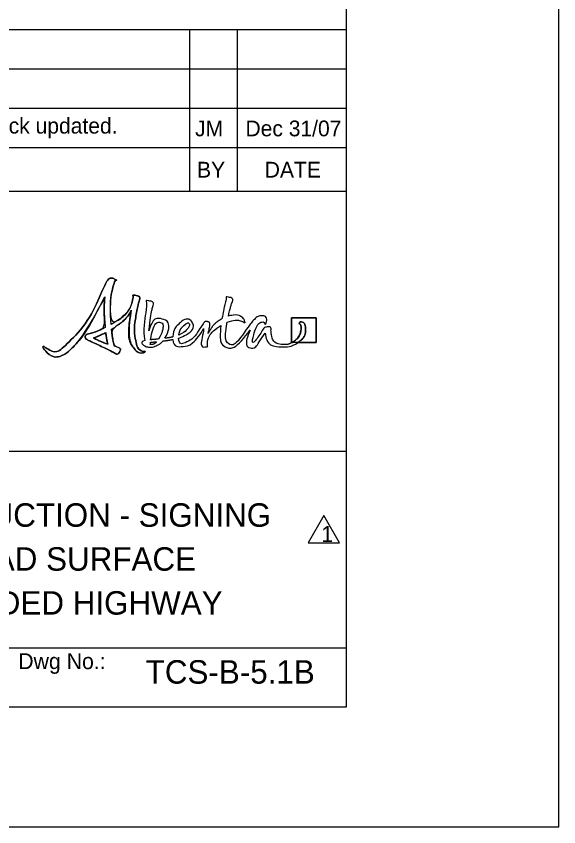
# Model space of a CAD drawing. Extents: x 1351 to 1567, y 178 to 457.
# Drawn here: x 1518.5 to 1567.4, y 177.9 to 251 of the extents above; entities that cross this region are included whole.
import ezdxf

# ---------------------------------------------------------------- set-up
doc = ezdxf.new("R2010")
doc.units = 0
doc.layers.add('Level 53', color=7, linetype='Continuous')
doc.layers.add('Level 60', color=7, linetype='Continuous')

msp = doc.modelspace()

# ---------------------------------------------------------------- linework, layer by layer
at = {"layer": 'Level 53'}
msp.add_line((1543.914, 221.573), (1543.364, 221.573), dxfattribs=at)
msp.add_lwpolyline([(1543.914, 221.573), (1545.53, 221.573), (1545.53, 223.804), (1543.3, 223.804), (1543.3, 221.573), (1543.364, 221.573)], dxfattribs=at)
for points, degree in [([(1529.929, 220.764), (1529.69, 220.8), (1529.375, 221.126), (1529.28, 221.663), (1529.109, 222.629), (1529.21, 223.583), (1529.494, 225.004), (1529.548, 225.273), (1529.732, 225.739), (1529.148, 225.829), (1528.963, 225.857), (1529.059, 225.766), (1529.007, 225.52), (1528.782, 224.461), (1527.917, 223.699), (1527.048, 223.188), (1526.957, 224.399), (1526.994, 225.745), (1527.222, 226.57), (1527.414, 227.266), (1527.643, 227.138), (1527.359, 227.285), (1527.061, 227.439), (1526.74, 227.235), (1526.48, 226.717), (1526.22, 226.198), (1525.023, 223.382), (1523.112, 221.482), (1522.134, 220.509), (1521.249, 221.01), (1521.072, 221.159), (1520.928, 221.281), (1520.875, 221.093), (1521.053, 220.901), (1521.845, 220.048), (1523, 220.537), (1523.421, 220.958), (1524.584, 222.12), (1525.936, 224.622), (1526.483, 225.684), (1526.432, 225.086), (1526.416, 224.083), (1526.527, 222.909), (1525.935, 222.62), (1525.404, 222.451), (1525.154, 222.385), (1524.883, 222.314), (1524.715, 222.203), (1524.71, 222.078), (1524.705, 221.94), (1524.887, 221.824), (1525.15, 221.699), (1525.619, 221.477), (1526.99, 220.829), (1527.328, 220.632), (1527.618, 220.464), (1527.759, 220.596), (1527.845, 220.777), (1527.957, 221.013), (1527.65, 221.149), (1527.352, 221.238), (1527.238, 221.636), (1527.146, 222.172), (1527.085, 222.762), (1527.783, 223.191), (1528.47, 223.763), (1528.865, 224.477), (1528.766, 223.88), (1528.51, 221.849), (1529.151, 220.991), (1529.292, 220.802), (1529.604, 220.595), (1529.908, 220.626), (1530.051, 220.64), (1530.124, 220.734), (1530.11, 220.764), (1530.095, 220.793), (1530.013, 220.752), (1529.929, 220.764)], 3), ([(1527.048, 223.188), (1526.957, 224.399), (1526.994, 225.745), (1527.222, 226.57), (1527.414, 227.266), (1527.643, 227.138), (1527.359, 227.285), (1527.061, 227.439), (1526.74, 227.235), (1526.48, 226.717), (1526.22, 226.198), (1525.023, 223.382), (1523.112, 221.482), (1522.134, 220.509), (1521.249, 221.01), (1521.072, 221.159), (1520.928, 221.281), (1520.875, 221.093), (1521.053, 220.901), (1521.845, 220.048), (1523, 220.537), (1523.421, 220.958), (1524.584, 222.12), (1525.936, 224.622), (1526.483, 225.684)], 3), ([(1529.929, 220.764), (1529.69, 220.8), (1529.375, 221.126), (1529.28, 221.663), (1529.109, 222.629), (1529.21, 223.583), (1529.494, 225.004), (1529.548, 225.273), (1529.732, 225.739), (1529.148, 225.829), (1528.963, 225.857), (1529.059, 225.766), (1529.007, 225.52), (1528.782, 224.461), (1527.917, 223.699), (1527.048, 223.188)], 3), ([(1526.483, 225.684), (1526.432, 225.086), (1526.416, 224.083), (1526.527, 222.909)], 2), ([(1530.466, 222.606), (1530.512, 223.174), (1530.603, 223.867), (1530.731, 224.51), (1530.785, 224.779), (1530.969, 225.244), (1530.385, 225.334), (1530.2, 225.363), (1530.228, 225.276), (1530.244, 225.025), (1530.265, 224.688), (1529.892, 222.649), (1530.086, 221.753)], 3), ([(1537.62, 223.947), (1537.685, 224.244), (1537.76, 224.546), (1537.843, 224.84), (1537.918, 225.109), (1538.139, 225.575), (1537.562, 225.664), (1537.379, 225.693), (1537.457, 225.604), (1537.396, 225.356), (1537.285, 224.898), (1537.144, 224.306), (1537.043, 223.71)], 3), ([(1527.085, 222.762), (1527.783, 223.191), (1528.47, 223.763), (1528.865, 224.477)], 2), ([(1528.865, 224.477), (1528.766, 223.88), (1528.51, 221.849), (1529.151, 220.991), (1529.292, 220.802), (1529.604, 220.595), (1529.908, 220.626), (1530.051, 220.64), (1530.124, 220.734), (1530.11, 220.764), (1530.095, 220.793), (1530.013, 220.752), (1529.929, 220.764)], 3), ([(1531.904, 221.944), (1532.318, 222.617), (1532.283, 223.527), (1531.676, 223.68), (1530.972, 223.858), (1530.616, 223.174), (1530.466, 222.606)], 3), ([(1533.13, 221.967), (1533.226, 221.996), (1533.312, 222.027), (1533.385, 222.059), (1534.268, 222.451), (1534.571, 223.041), (1534.347, 223.4), (1534.134, 223.741), (1533.525, 223.638), (1533.044, 223.131), (1532.807, 222.882), (1532.625, 222.453), (1532.604, 222.063)], 3), ([(1537.043, 223.71), (1536.569, 223.437), (1536.128, 222.981), (1535.804, 222.381)], 2), ([(1542.675, 221.375), (1541.759, 221.375), (1541.523, 222.087), (1541.479, 222.439), (1541.45, 222.673), (1541.5, 223.012), (1541.096, 222.967), (1540.813, 222.935), (1540.557, 222.384), (1540.198, 221.92), (1539.89, 221.521), (1539.752, 221.559), (1539.824, 221.902), (1539.913, 222.33), (1540.27, 223.335), (1540.68, 223.409), (1540.869, 223.442), (1540.936, 223.11), (1541.023, 223.318), (1541.111, 223.526), (1541.031, 223.976), (1540.607, 223.976), (1540.311, 223.976), (1539.955, 223.662), (1539.663, 223.304), (1539.409, 222.992), (1538.124, 221.1), (1537.585, 221.508), (1537.333, 221.699), (1537.353, 222.477), (1537.512, 223.393)], 3), ([(1537.512, 223.393), (1538.151, 223.639), (1538.683, 223.559), (1538.984, 223.414), (1539.133, 223.343), (1539.153, 223.353), (1539.09, 223.517), (1538.996, 223.757), (1538.482, 224.132), (1537.678, 223.96), (1537.659, 223.956), (1537.639, 223.951), (1537.62, 223.947)], 3), ([(1543.3, 223.804), (1543.3, 223.804), (1543.3, 221.573), (1543.3, 221.573), (1543.3, 221.573), (1543.364, 221.573), (1543.364, 221.573), (1543.848, 221.863), (1544.174, 222.417), (1544.173, 222.873), (1544.173, 223.267), (1543.964, 223.247), (1543.988, 223.302), (1544.055, 223.46), (1544.548, 223.37), (1544.577, 222.814), (1544.601, 222.342), (1544.354, 221.886), (1543.914, 221.573), (1543.914, 221.573), (1545.53, 221.573), (1545.53, 221.573), (1545.53, 221.573), (1545.53, 223.804), (1545.53, 223.804), (1545.53, 223.804), (1543.3, 223.804), (1543.3, 223.804)], 3), ([(1526.527, 222.909), (1525.935, 222.62), (1525.404, 222.451), (1525.154, 222.385), (1524.883, 222.314), (1524.715, 222.203), (1524.71, 222.078), (1524.705, 221.94), (1524.887, 221.824), (1525.15, 221.699), (1525.619, 221.477), (1526.99, 220.829), (1527.328, 220.632), (1527.618, 220.464), (1527.759, 220.596), (1527.845, 220.777), (1527.957, 221.013), (1527.65, 221.149), (1527.352, 221.238)], 3), ([(1530.616, 221.815), (1530.711, 222.531), (1531.083, 223.526), (1531.547, 223.366), (1531.814, 223.274), (1531.674, 222.435), (1531.331, 221.878)], 3), ([(1532.61, 221.842), (1532.659, 221.449), (1532.915, 221.148), (1533.51, 221.203), (1534.357, 221.282), (1535.108, 222.322), (1535.392, 222.823)], 3), ([(1535.804, 222.381), (1535.86, 222.658), (1535.947, 222.964), (1535.953, 223.17), (1535.959, 223.388), (1535.81, 223.436), (1535.752, 223.453), (1535.626, 223.489), (1535.473, 223.426), (1535.322, 223.213), (1534.969, 222.716), (1534.522, 221.929), (1533.843, 221.598), (1533.356, 221.362), (1533.142, 221.6), (1533.13, 221.967)], 3), ([(1533.602, 223.086), (1533.898, 223.361), (1534.045, 223.341), (1534.084, 223.267), (1534.168, 223.108), (1533.819, 222.545), (1533.152, 222.237)], 3), ([(1533.152, 222.237), (1533.21, 222.54), (1533.369, 222.87), (1533.602, 223.086)], 2), ([(1535.392, 222.823), (1535.341, 222.286), (1534.991, 221.113), (1535.587, 221.173), (1535.821, 221.197), (1535.719, 221.234), (1535.734, 221.436), (1535.785, 222.142), (1536.373, 222.741), (1536.955, 223.108)], 3), ([(1536.955, 223.108), (1536.854, 222.243), (1536.889, 221.47), (1537.282, 221.225), (1538.004, 220.773), (1539.026, 221.962), (1539.589, 222.689)], 3), ([(1543.364, 221.573), (1543.848, 221.863), (1544.174, 222.417), (1544.173, 222.873), (1544.173, 223.267), (1543.964, 223.247), (1543.988, 223.302), (1544.055, 223.46), (1544.548, 223.37), (1544.577, 222.814), (1544.601, 222.342), (1544.354, 221.886), (1543.914, 221.573)], 3), ([(1525.457, 221.976), (1525.766, 222.089), (1526.159, 222.254), (1526.573, 222.471)], 2), ([(1525.457, 221.976), (1525.766, 222.089), (1526.159, 222.254), (1526.573, 222.471), (1526.629, 221.998), (1526.69, 221.655), (1526.757, 221.402), (1526.454, 221.512), (1526.022, 221.688), (1525.457, 221.976)], 3), ([(1526.573, 222.471), (1526.629, 221.998), (1526.69, 221.655), (1526.757, 221.402)], 2), ([(1527.352, 221.238), (1527.238, 221.636), (1527.146, 222.172), (1527.085, 222.762)], 2), ([(1539.589, 222.689), (1539.302, 222.044), (1539.14, 221.216), (1539.571, 221.09), (1540.075, 220.943), (1540.473, 221.78), (1540.939, 222.421)], 3), ([(1540.939, 222.421), (1540.993, 221.961), (1541.3, 221.168), (1542.537, 221.168), (1543.093, 221.168), (1543.565, 221.325), (1543.914, 221.573)], 3), ([(1526.757, 221.402), (1526.454, 221.512), (1526.022, 221.688), (1525.457, 221.976)], 2), ([(1530.086, 221.753), (1529.835, 221.672), (1529.733, 221.483), (1530.056, 221.284), (1530.279, 221.146), (1530.769, 221.101), (1531.264, 221.345), (1531.441, 221.432), (1531.595, 221.555), (1531.723, 221.7)], 3), ([(1530.541, 221.383), (1530.573, 221.41), (1530.593, 221.45), (1530.593, 221.498), (1530.593, 221.529), (1530.594, 221.561), (1530.595, 221.593)], 3), ([(1530.743, 221.384), (1530.661, 221.372), (1530.594, 221.373), (1530.541, 221.383)], 2), ([(1530.595, 221.593), (1530.721, 221.599), (1530.918, 221.613), (1531.152, 221.636)], 2), ([(1531.331, 221.878), (1531.106, 221.855), (1530.868, 221.834), (1530.616, 221.815)], 2), ([(1531.152, 221.636), (1531.029, 221.501), (1530.891, 221.407), (1530.743, 221.384)], 2), ([(1531.723, 221.7), (1532.018, 221.738), (1532.328, 221.785), (1532.61, 221.842)], 2), ([(1532.604, 222.063), (1532.4, 222.018), (1532.165, 221.979), (1531.904, 221.944)], 2), ([(1543.364, 221.573), (1543.159, 221.451), (1542.925, 221.375), (1542.675, 221.375)], 2)]:
    msp.add_open_spline(points, degree=degree, dxfattribs=at)
at = {"layer": 'Level 60'}
for p, q in [((1548.312, 249.746), (1484.432, 249.746)), ((1548.312, 249.746), (1484.432, 249.746)), ((1534.118, 249.746), (1534.118, 235.196)), ((1534.118, 249.746), (1534.118, 235.196)), ((1538.429, 249.746), (1538.429, 235.196)), ((1538.429, 249.746), (1538.429, 235.196)), ((1548.312, 246.197), (1484.432, 246.197)), ((1548.312, 246.197), (1484.432, 246.197)), ((1548.312, 242.648), (1484.432, 242.648)), ((1548.312, 242.648), (1484.432, 242.648)), ((1548.312, 239.1), (1484.432, 239.1)), ((1548.312, 239.1), (1484.432, 239.1)), ((1484.439, 235.196), (1548.312, 235.196)), ((1484.439, 235.196), (1548.312, 235.196)), ((1518.505, 235.196), (1518.505, 235.196)), ((1518.505, 235.196), (1518.505, 235.196)), ((1484.439, 211.787), (1548.282, 211.787)), ((1484.439, 194.053), (1548.282, 194.053)), ((1548.282, 188.732), (1548.282, 188.732)), ((1548.282, 188.732), (1548.282, 188.732))]:
    msp.add_line(p, q, dxfattribs=at)
for points in [[(1567.408, 456.923), (1351.408, 456.923), (1351.408, 177.923), (1567.408, 177.923)], [(1548.282, 446.114), (1361.408, 446.114), (1361.408, 188.732), (1548.282, 188.732)], [(1546.223, 205.987), (1544.804, 203.517), (1547.642, 203.517)]]:
    msp.add_lwpolyline(points, close=True, dxfattribs=at)

# ---------------------------------------------------------------- texts
for s, height, p in [('Note added and Title Block updated.', 1.419, (1496.933, 240.394)), ('TCS-B-5.1B', 2.115, (1530.168, 190.822))]:
    msp.add_text(s, height=height, dxfattribs=at).set_placement(p)
for s, height, rotation, p in [('JM', 1.4189, 360, (1534.622, 240.149)), ('JM', 1.4189, 360, (1534.622, 240.149)), ('Dec 31/07', 1.4189, 360, (1539.163, 240.149)), ('Dec 31/07', 1.4189, 360, (1539.163, 240.149)), ('BY', 1.4194, 360, (1534.8, 236.431)), ('BY', 1.4194, 360, (1534.8, 236.431)), ('DATE', 1.4194, 360, (1540.902, 236.431)), ('DATE', 1.4194, 360, (1540.902, 236.431)), ('UTILITIES CONSTRUCTION - SIGNING', 2.115, 359.99999, (1490.256, 204.961)), ('1', 1.448, 360, (1545.996, 203.574)), ('WORK OFF ROAD SURFACE', 2.115, 359.99999, (1496.21, 201.002)), ('FOUR LANE DIVIDED HIGHWAY', 2.115, 359.99999, (1494.361, 197.042)), ('Dwg No.:', 1.4329, 360, (1518.681, 192.131))]:
    msp.add_text(s, height=height, rotation=rotation, dxfattribs=at).set_placement(p)

doc.saveas('drawing.dxf')
